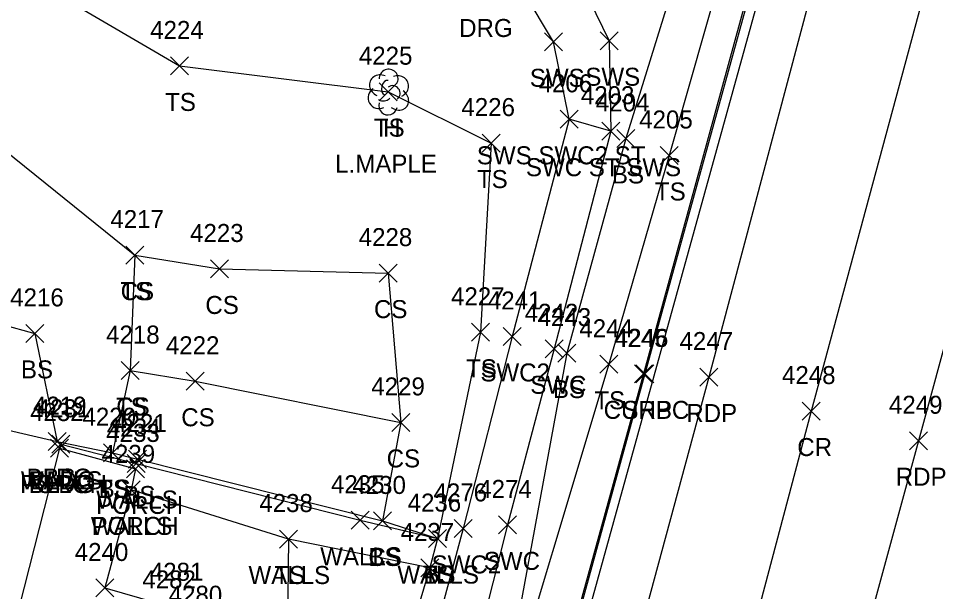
# Model space of a CAD drawing. Extents: x 1443912 to 1445411, y 621446 to 623693.
# Drawn here: x 1444888.1 to 1444990, y 623392.4 to 623456.1 of the extents above; entities that cross this region are included whole.
import ezdxf

# ---------------------------------------------------------------- set-up
doc = ezdxf.new("R2010")
doc.units = 0
for name, color, linetype in [('DCP', 7, 'Continuous'), ('L_A', 7, 'Continuous'), ('L_C', 7, 'Continuous'), ('L_I', 7, 'Continuous'), ('L_TIC', 7, 'Continuous'), ('LBC', 7, 'Continuous'), ('LBF', 7, 'Continuous'), ('LELB', 7, 'Continuous'), ('LTD', 7, 'Continuous'), ('LWS', 7, 'Continuous'), ('P_A', 7, 'Continuous'), ('P_I', 7, 'Continuous'), ('P_TIC', 7, 'Continuous'), ('PET', 7, 'Continuous'), ('PRC', 7, 'Continuous'), ('PSP', 7, 'Continuous'), ('R_A', 7, 'Continuous'), ('R_I', 7, 'Continuous'), ('R_TIC', 7, 'Continuous'), ('RC', 7, 'Continuous'), ('RSW', 7, 'Continuous')]:
    doc.layers.add(name, color=color, linetype=linetype)

msp = doc.modelspace()

# ---------------------------------------------------------------- linework, layer by layer
at = {"layer": 'DCP'}
msp.add_lwpolyline([(1444991.54, 623534.89), (1444942.32, 623357.04)], dxfattribs=at)
at = {"layer": 'L_TIC'}
for points in [[(1444905.02, 623449.79), (1444907.02, 623451.79)], [(1444907.02, 623449.79), (1444905.02, 623451.79)], [(1444928.21, 623446.93), (1444930.21, 623448.93)], [(1444930.21, 623446.93), (1444928.21, 623448.93)], [(1444939.66, 623441.22), (1444941.66, 623443.22)], [(1444941.66, 623441.22), (1444939.66, 623443.22)], [(1444954.62, 623441.73), (1444956.62, 623443.73)], [(1444956.62, 623441.73), (1444954.62, 623443.73)], [(1444959.43, 623439.84), (1444961.43, 623441.84)], [(1444961.43, 623439.84), (1444959.43, 623441.84)], [(1444900.05, 623428.77), (1444902.05, 623430.77)], [(1444902.05, 623428.77), (1444900.05, 623430.77)], [(1444900.05, 623428.77), (1444902.05, 623430.77)], [(1444902.05, 623428.77), (1444900.05, 623430.77)], [(1444909.46, 623427.23), (1444911.46, 623429.23)], [(1444911.46, 623427.23), (1444909.46, 623429.23)], [(1444928.19, 623426.77), (1444930.19, 623428.77)], [(1444930.19, 623426.77), (1444928.19, 623428.77)], [(1444888.96, 623420.07), (1444890.96, 623422.07)], [(1444890.96, 623420.07), (1444888.96, 623422.07)], [(1444938.45, 623420.19), (1444940.45, 623422.19)], [(1444940.45, 623420.19), (1444938.45, 623422.19)], [(1444948.06, 623417.88), (1444950.06, 623419.88)], [(1444950.06, 623417.88), (1444948.06, 623419.88)], [(1444899.56, 623415.94), (1444901.56, 623417.94)], [(1444901.56, 623415.94), (1444899.56, 623417.94)], [(1444899.56, 623415.94), (1444901.56, 623417.94)], [(1444901.56, 623415.94), (1444899.56, 623417.94)], [(1444952.7, 623416.64), (1444954.7, 623418.64)], [(1444954.7, 623416.64), (1444952.7, 623418.64)], [(1444906.77, 623414.75), (1444908.77, 623416.75)], [(1444908.77, 623414.75), (1444906.77, 623416.75)], [(1444929.6, 623410.18), (1444931.6, 623412.18)], [(1444931.6, 623410.18), (1444929.6, 623412.18)], [(1444929.6, 623410.18), (1444931.6, 623412.18)], [(1444931.6, 623410.18), (1444929.6, 623412.18)], [(1444891.45, 623408.04), (1444893.45, 623410.04)], [(1444893.45, 623408.04), (1444891.45, 623410.04)], [(1444891.45, 623408.04), (1444893.45, 623410.04)], [(1444893.45, 623408.04), (1444891.45, 623410.04)], [(1444891.85, 623407.75), (1444893.85, 623409.75)], [(1444893.85, 623407.75), (1444891.85, 623409.75)], [(1444891.85, 623407.75), (1444893.85, 623409.75)], [(1444893.85, 623407.75), (1444891.85, 623409.75)], [(1444891.69, 623407.33), (1444893.69, 623409.33)], [(1444893.69, 623407.33), (1444891.69, 623409.33)], [(1444891.69, 623407.33), (1444893.69, 623409.33)], [(1444893.69, 623407.33), (1444891.69, 623409.33)], [(1444897.59, 623406.81), (1444899.59, 623408.81)], [(1444899.59, 623406.81), (1444897.59, 623408.81)], [(1444897.59, 623406.81), (1444899.59, 623408.81)], [(1444899.59, 623406.81), (1444897.59, 623408.81)], [(1444900.22, 623405.61), (1444902.22, 623407.61)], [(1444902.22, 623405.61), (1444900.22, 623407.61)], [(1444900.35, 623406.11), (1444902.35, 623408.11)], [(1444902.35, 623406.11), (1444900.35, 623408.11)], [(1444900.14, 623405.01), (1444902.14, 623407.01)], [(1444902.14, 623405.01), (1444900.14, 623407.01)], [(1444899.64, 623402.68), (1444901.64, 623404.68)], [(1444901.64, 623402.68), (1444899.64, 623404.68)], [(1444899.64, 623402.68), (1444901.64, 623404.68)], [(1444901.64, 623402.68), (1444899.64, 623404.68)], [(1444925.11, 623399.31), (1444927.11, 623401.31)], [(1444927.11, 623399.31), (1444925.11, 623401.31)], [(1444927.57, 623399.23), (1444929.57, 623401.23)], [(1444929.57, 623399.23), (1444927.57, 623401.23)], [(1444927.57, 623399.23), (1444929.57, 623401.23)], [(1444929.57, 623399.23), (1444927.57, 623401.23)], [(1444917.15, 623397.22), (1444919.15, 623399.22)], [(1444919.15, 623397.22), (1444917.15, 623399.22)], [(1444917.15, 623397.22), (1444919.15, 623399.22)], [(1444919.15, 623397.22), (1444917.15, 623399.22)], [(1444933.68, 623397.27), (1444935.68, 623399.27)], [(1444935.68, 623397.27), (1444933.68, 623399.27)], [(1444933.68, 623397.27), (1444935.68, 623399.27)], [(1444935.68, 623397.27), (1444933.68, 623399.27)], [(1444933.68, 623397.27), (1444935.68, 623399.27)], [(1444935.68, 623397.27), (1444933.68, 623399.27)], [(1444932.85, 623394.01), (1444934.85, 623396.01)], [(1444934.85, 623394.01), (1444932.85, 623396.01)], [(1444932.85, 623394.01), (1444934.85, 623396.01)], [(1444934.85, 623394.01), (1444932.85, 623396.01)], [(1444896.74, 623391.78), (1444898.74, 623393.78)], [(1444898.74, 623391.78), (1444896.74, 623393.78)]]:
    msp.add_lwpolyline(points, dxfattribs=at)
at = {"layer": 'LBC'}
msp.add_lwpolyline([(1444874.93, 623413.13), (1444892.45, 623409.04), (1444892.85, 623408.75), (1444892.69, 623408.33), (1444883.66, 623372.89), (1444883.63, 623372.57), (1444883.28, 623372.4), (1444880.79, 623373.15), (1444876.87, 623374.34), (1444869.22, 623376.28)], dxfattribs=at)
at = {"layer": 'LBF'}
msp.add_lwpolyline([(1444892.69, 623408.33), (1444901.14, 623406.01), (1444900.64, 623403.68), (1444897.74, 623392.78), (1444905.42, 623390.58), (1444905.16, 623389.73)], dxfattribs=at)
at = {"layer": 'LELB'}
for points in [[(1444999.5, 623624.29), (1445006.38, 623617.23), (1444999.2, 623587.78), (1444986.64, 623540.21), (1444984.08, 623533.25), (1444978.9, 623513.73), (1444970.81, 623477.4), (1444960.43, 623440.84), (1444953.7, 623417.64), (1444941.08, 623375.56)], [(1444955.52, 623511.73), (1444964.94, 623508.39), (1444968.01, 623499.55), (1444966.57, 623478.12), (1444955.62, 623442.73), (1444949.06, 623418.88), (1444941.08, 623375.56)], [(1444888.4, 623461.15), (1444906.02, 623450.79), (1444929.21, 623447.93), (1444940.66, 623442.22), (1444939.45, 623421.19), (1444934.68, 623398.27)], [(1444884.37, 623443.21), (1444901.05, 623429.77), (1444910.46, 623428.23), (1444929.19, 623427.77), (1444930.6, 623411.18), (1444928.57, 623400.23)], [(1444901.05, 623429.77), (1444900.56, 623416.94), (1444898.59, 623407.81)], [(1444878.71, 623424.16), (1444889.96, 623421.07), (1444892.45, 623409.04), (1444898.59, 623407.81), (1444901.35, 623407.11), (1444928.57, 623400.23), (1444934.68, 623398.27)], [(1444900.56, 623416.94), (1444907.77, 623415.75), (1444930.6, 623411.18)], [(1444918.15, 623398.22), (1444917.97, 623385.55), (1444916.8, 623381.05), (1444910.37, 623369.23)], [(1444933.85, 623395.01), (1444930.13, 623382.54), (1444929.89, 623377.57), (1444926.05, 623365.16)]]:
    msp.add_lwpolyline(points, dxfattribs=at)
at = {"layer": 'LTD'}
msp.add_line((1444929.21, 623447.93), (1444929.21, 623447.93), dxfattribs=at)
msp.add_line((1444929.21, 623447.93), (1444929.21, 623447.93), dxfattribs=at)
msp.add_arc((1444929.26, 623449.37), 1.05, 335.5272, 180.9563, dxfattribs=at)
for centre, major_axis, ratio, start_param, end_param in [((1444928.42, 623448.6), (1.21, -0.51), 0.895232, 1.570796, 4.712389), ((1444930.25, 623448.52), (-1.14, -0.48), 0.949671, 1.570796, 4.712389), ((1444929, 623448.39), (-0.208, -0.792), 0.645439, 3.141593, 6.283185), ((1444929.71, 623447.77), (-0.5, 0.667), 0.989748, 3.141593, 6.283185), ((1444928.13, 623447.22), (0.58, -1.04), 0.959034, 3.141593, 6.283185), ((1444928.75, 623447.18), (-0.625, -0.083), 0.423636, 0, 3.141593), ((1444930.21, 623447.1), (-1.09, 0.79), 0.841452, 1.570796, 4.712389), ((1444929.21, 623446.43), (0.26, 1.06), 0.942809, 1.570796, 4.712389)]:
    msp.add_ellipse(centre, major_axis=major_axis, ratio=ratio, start_param=start_param, end_param=end_param, dxfattribs=at)
at = {"layer": 'LWS'}
msp.add_lwpolyline([(1444892.85, 623408.75), (1444901.22, 623406.61), (1444926.11, 623400.31), (1444934.68, 623398.27), (1444933.85, 623395.01), (1444918.15, 623398.22), (1444900.64, 623403.68)], dxfattribs=at)
at = {"layer": 'P_TIC'}
for points in [[(1444956.7, 623415.57), (1444958.7, 623417.57)], [(1444958.7, 623415.57), (1444956.7, 623417.57)], [(1444963.83, 623415.22), (1444965.83, 623417.22)], [(1444965.83, 623415.22), (1444963.83, 623417.22)], [(1444975.21, 623411.44), (1444977.21, 623413.44)], [(1444977.21, 623411.44), (1444975.21, 623413.44)], [(1444987.1, 623408.14), (1444989.1, 623410.14)], [(1444989.1, 623408.14), (1444987.1, 623410.14)]]:
    msp.add_lwpolyline(points, dxfattribs=at)
at = {"layer": 'PET'}
for points in [[(1445036.7, 623677.7), (1445026.38, 623639.78), (1445008.65, 623576.15), (1444996.95, 623532.89), (1444979.78, 623472.47), (1444964.83, 623416.22), (1444955.71, 623382.54), (1444949.17, 623358.13), (1444939.29, 623323.43), (1444926.27, 623275.91), (1444914.83, 623235.04), (1444901.53, 623186.46), (1444892.14, 623152.69), (1444883.14, 623119.13), (1444870.13, 623073.23), (1444861.49, 623043.31), (1444850.84, 623006.82), (1444834.61, 622954.83), (1444817.28, 622898.33)], [(1445060.04, 623670.52), (1445049.49, 623631.42), (1445031.61, 623567.44), (1445020.44, 623527.05), (1445003.5, 623465.59), (1444988.1, 623409.14), (1444976.63, 623367.03), (1444962.49, 623315.05), (1444949.49, 623267.35), (1444937.78, 623225.39), (1444926.09, 623182.22), (1444915.48, 623145.05), (1444906.98, 623113.48), (1444893.64, 623066.1), (1444886.06, 623037.31), (1444876.58, 623001.08), (1444863.33, 622947.05), (1444849.43, 622890.74)]]:
    msp.add_lwpolyline(points, dxfattribs=at)
at = {"layer": 'PRC'}
msp.add_lwpolyline([(1445048.12, 623674.07), (1445038.05, 623635.88), (1445020.14, 623572.7), (1445008.5, 623529.11), (1444991.68, 623469.75), (1444976.21, 623412.44), (1444964.87, 623369.69), (1444950.64, 623318.47), (1444938.05, 623272.58), (1444925.39, 623227.3), (1444913.85, 623184.57), (1444903.74, 623148.67), (1444894.97, 623116.18), (1444881.8, 623068.92), (1444873.97, 623040.25), (1444864.1, 623005.34), (1444846.73, 622950.74), (1444829.37, 622896.11)], dxfattribs=at)
at = {"layer": 'PSP'}
msp.add_lwpolyline([(1445029.6, 623678.26), (1445021.68, 623649.55), (1445019.78, 623642.34), (1445019.32, 623640.93), (1445017.21, 623633.02), (1445017.08, 623631.73), (1445013.01, 623618.17), (1445011.68, 623612.99), (1445004.58, 623587.1), (1444990.43, 623535.38), (1444989.65, 623532.72), (1444983.26, 623509.22), (1444982.17, 623505.29), (1444973.63, 623474.39), (1444957.7, 623416.57), (1444946.06, 623374.16), (1444939.52, 623351.37), (1444938.45, 623347.36), (1444929.03, 623313.43)], dxfattribs=at)
at = {"layer": 'R_TIC'}
for points in [[(1444946.57, 623452.47), (1444948.57, 623454.47)], [(1444948.57, 623452.47), (1444946.57, 623454.47)], [(1444952.74, 623452.59), (1444954.74, 623454.59)], [(1444954.74, 623452.59), (1444952.74, 623454.59)], [(1444948.32, 623443.86), (1444950.32, 623445.86)], [(1444950.32, 623443.86), (1444948.32, 623445.86)], [(1444948.32, 623443.86), (1444950.32, 623445.86)], [(1444950.32, 623443.86), (1444948.32, 623445.86)], [(1444952.94, 623442.54), (1444954.94, 623444.54)], [(1444954.94, 623442.54), (1444952.94, 623444.54)], [(1444952.94, 623442.54), (1444954.94, 623444.54)], [(1444954.94, 623442.54), (1444952.94, 623444.54)], [(1444941.98, 623419.73), (1444943.98, 623421.73)], [(1444943.98, 623419.73), (1444941.98, 623421.73)], [(1444946.63, 623418.36), (1444948.63, 623420.36)], [(1444948.63, 623418.36), (1444946.63, 623420.36)], [(1444956.56, 623415.57), (1444958.56, 623417.57)], [(1444958.56, 623415.57), (1444956.56, 623417.57)], [(1444936.55, 623398.4), (1444938.55, 623400.4)], [(1444938.55, 623398.4), (1444936.55, 623400.4)], [(1444941.47, 623398.79), (1444943.47, 623400.79)], [(1444943.47, 623398.79), (1444941.47, 623400.79)]]:
    msp.add_lwpolyline(points, dxfattribs=at)
at = {"layer": 'RC'}
msp.add_lwpolyline([(1444983.26, 623509.22), (1444981.83, 623505.36), (1444973.42, 623474.46), (1444957.56, 623416.57), (1444945.85, 623374.13), (1444939.35, 623351.65), (1444938.45, 623347.36)], dxfattribs=at)
at = {"layer": 'RSW'}
for points in [[(1444942.3, 623469.71), (1444949.28, 623462.8), (1444953.74, 623453.59), (1444953.94, 623443.54), (1444949.32, 623444.86), (1444947.57, 623453.47), (1444941.15, 623464.23)], [(1444949.32, 623444.86), (1444942.98, 623420.73), (1444937.55, 623399.4), (1444932.87, 623382.02), (1444930.13, 623382.54), (1444917.97, 623385.55), (1444908.17, 623388.03), (1444905.16, 623389.73), (1444903.6, 623383.28), (1444916.8, 623381.05), (1444929.89, 623377.57), (1444931.56, 623377.29), (1444926.2, 623354.92), (1444902.49, 623360.19), (1444873.29, 623366.86), (1444874.21, 623370.22), (1444875.65, 623369.85), (1444876.87, 623374.34)], [(1444953.94, 623443.54), (1444947.63, 623419.36), (1444942.47, 623399.79), (1444937.61, 623380.62), (1444930.5, 623354.09)]]:
    msp.add_lwpolyline(points, dxfattribs=at)

# ---------------------------------------------------------------- texts
at = {"layer": 'L_A'}
for s, p in [('TS', (1444904.43, 623445.79)), ('TS', (1444927.62, 623442.93)), ('H', (1444928.65, 623442.93)), ('TS', (1444939.07, 623437.22)), ('BS', (1444954.06, 623437.73)), ('TS', (1444958.84, 623435.84)), ('TS', (1444899.46, 623424.77)), ('CS', (1444899.49, 623424.77)), ('CS', (1444908.9, 623423.23)), ('CS', (1444927.63, 623422.77)), ('BS', (1444888.41, 623416.07)), ('TS', (1444937.86, 623416.19)), ('BS', (1444947.5, 623413.88)), ('TS', (1444952.11, 623412.64)), ('TS', (1444898.97, 623411.94)), ('CS', (1444899, 623411.94)), ('CS', (1444906.22, 623410.75)), ('CS', (1444929.04, 623406.18)), ('CS', (1444929.04, 623406.18)), ('WALLS', (1444888.4, 623403.75)), ('BLDG', (1444889.04, 623404.04)), ('BLDG', (1444889.44, 623403.75)), ('BS', (1444890.89, 623404.04)), ('PORCH', (1444888.31, 623403.33)), ('BLDG', (1444889.28, 623403.33)), ('TS', (1444897, 623402.81)), ('BS', (1444897.04, 623402.81)), ('WALLS', (1444896.77, 623401.61)), ('BS', (1444899.79, 623402.11)), ('PORCH', (1444896.77, 623401.01)), ('WALLS', (1444896.18, 623398.68)), ('PORCH', (1444896.26, 623398.68)), ('WALLS', (1444921.65, 623395.31)), ('CS', (1444927.01, 623395.23)), ('BS', (1444927.01, 623395.23)), ('WALLS', (1444930.23, 623393.27)), ('TS', (1444933.09, 623393.27)), ('BS', (1444933.12, 623393.27)), ('WALLS', (1444913.69, 623393.22)), ('TS', (1444916.56, 623393.22))]:
    msp.add_text(s, height=2, dxfattribs=at).set_placement(p)
at = {"layer": 'L_C'}
msp.add_text('L.MAPLE', height=2, dxfattribs=at).set_placement((1444923.32, 623438.93))
at = {"layer": 'L_I'}
for s, p in [('4224', (1444902.77, 623453.79)), ('4225', (1444925.95, 623450.93)), ('4225', (1444925.95, 623450.93)), ('4204', (1444952.28, 623445.73)), ('4226', (1444937.34, 623445.22)), ('4205', (1444957.09, 623443.84)), ('4217', (1444898.35, 623432.77)), ('4217', (1444898.35, 623432.77)), ('4223', (1444907.2, 623431.23)), ('4228', (1444925.93, 623430.77)), ('4216', (1444887.22, 623424.07)), ('4227', (1444936.19, 623424.19)), ('4243', (1444945.8, 623421.88)), ('4218', (1444897.87, 623419.94)), ('4218', (1444897.87, 623419.94)), ('4244', (1444950.44, 623420.64)), ('4222', (1444904.51, 623418.75)), ('4229', (1444927.33, 623414.18)), ('4229', (1444927.33, 623414.18)), ('4219', (1444889.75, 623412.04)), ('4219', (1444889.75, 623412.04)), ('4231', (1444890.16, 623411.75)), ('4231', (1444890.16, 623411.75)), ('4232', (1444889.43, 623411.33)), ('4232', (1444889.43, 623411.33)), ('4220', (1444895.25, 623410.81)), ('4220', (1444895.25, 623410.81)), ('4234', (1444897.96, 623409.61)), ('4221', (1444898.66, 623410.11)), ('4233', (1444897.88, 623409.01)), ('4239', (1444897.37, 623406.68)), ('4239', (1444897.37, 623406.68)), ('4235', (1444922.85, 623403.31)), ('4230', (1444925.23, 623403.23)), ('4230', (1444925.23, 623403.23)), ('4238', (1444914.89, 623401.22)), ('4238', (1444914.89, 623401.22)), ('4236', (1444931.37, 623401.27)), ('4236', (1444931.37, 623401.27)), ('4236', (1444931.37, 623401.27)), ('4237', (1444930.59, 623398.01)), ('4237', (1444930.59, 623398.01)), ('4240', (1444894.39, 623395.78)), ('4281', (1444902.73, 623393.58)), ('4282', (1444901.9, 623392.73))]:
    msp.add_text(s, height=2, dxfattribs=at).set_placement(p)
at = {"layer": 'P_A'}
for s, p in [('SHP', (1444955.23, 623411.57)), ('RDP', (1444962.32, 623411.22)), ('CR', (1444974.65, 623407.44)), ('RDP', (1444985.59, 623404.14))]:
    msp.add_text(s, height=2, dxfattribs=at).set_placement(p)
at = {"layer": 'P_I'}
for s, p in [('4246', (1444954.38, 623419.57)), ('4247', (1444961.57, 623419.22)), ('4248', (1444972.95, 623415.44)), ('4249', (1444984.83, 623412.14))]:
    msp.add_text(s, height=2, dxfattribs=at).set_placement(p)
at = {"layer": 'R_A'}
for s, p in [('DRG', (1444937.09, 623454.01)), ('SWS', (1444944.94, 623448.47)), ('SWS', (1444951.11, 623448.59)), ('SWS SWC2 ST', (1444939.06, 623439.86)), ('SWS SWC2 ST', (1444939.06, 623439.86)), ('SWC ST SWS', (1444944.51, 623438.54)), ('SWC ST SWS', (1444944.51, 623438.54)), ('SWC2', (1444939.45, 623415.73)), ('SWC', (1444944.99, 623414.36)), ('CURBC', (1444953.14, 623411.57)), ('SWC2', (1444934.03, 623394.4)), ('SWC', (1444939.83, 623394.79))]:
    msp.add_text(s, height=2, dxfattribs=at).set_placement(p)
at = {"layer": 'R_I'}
for s, p in [('4206', (1444945.92, 623447.86)), ('4206', (1444945.92, 623447.86)), ('4203', (1444950.61, 623446.54)), ('4203', (1444950.61, 623446.54)), ('4241', (1444940.28, 623423.73)), ('4242', (1444944.37, 623422.36)), ('4245', (1444954.3, 623419.57)), ('4274', (1444939.21, 623402.79)), ('4276', (1444934.24, 623402.4)), ('4282', (1444901.9, 623392.73)), ('4280', (1444904.82, 623391.03))]:
    msp.add_text(s, height=2, dxfattribs=at).set_placement(p)

doc.saveas('drawing.dxf')
